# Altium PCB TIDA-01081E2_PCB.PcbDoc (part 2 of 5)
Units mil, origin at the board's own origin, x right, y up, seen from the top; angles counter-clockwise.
Board outline 8611.33 x 3169.64 mil, 4 copper layers (Top Layer, VCC, GND, Bottom Layer), stack 61.6 mil thick; 411 components, 187 nets, 1087 pads, 1987 vias.
Unrouted connection lines stored in the file: 7.
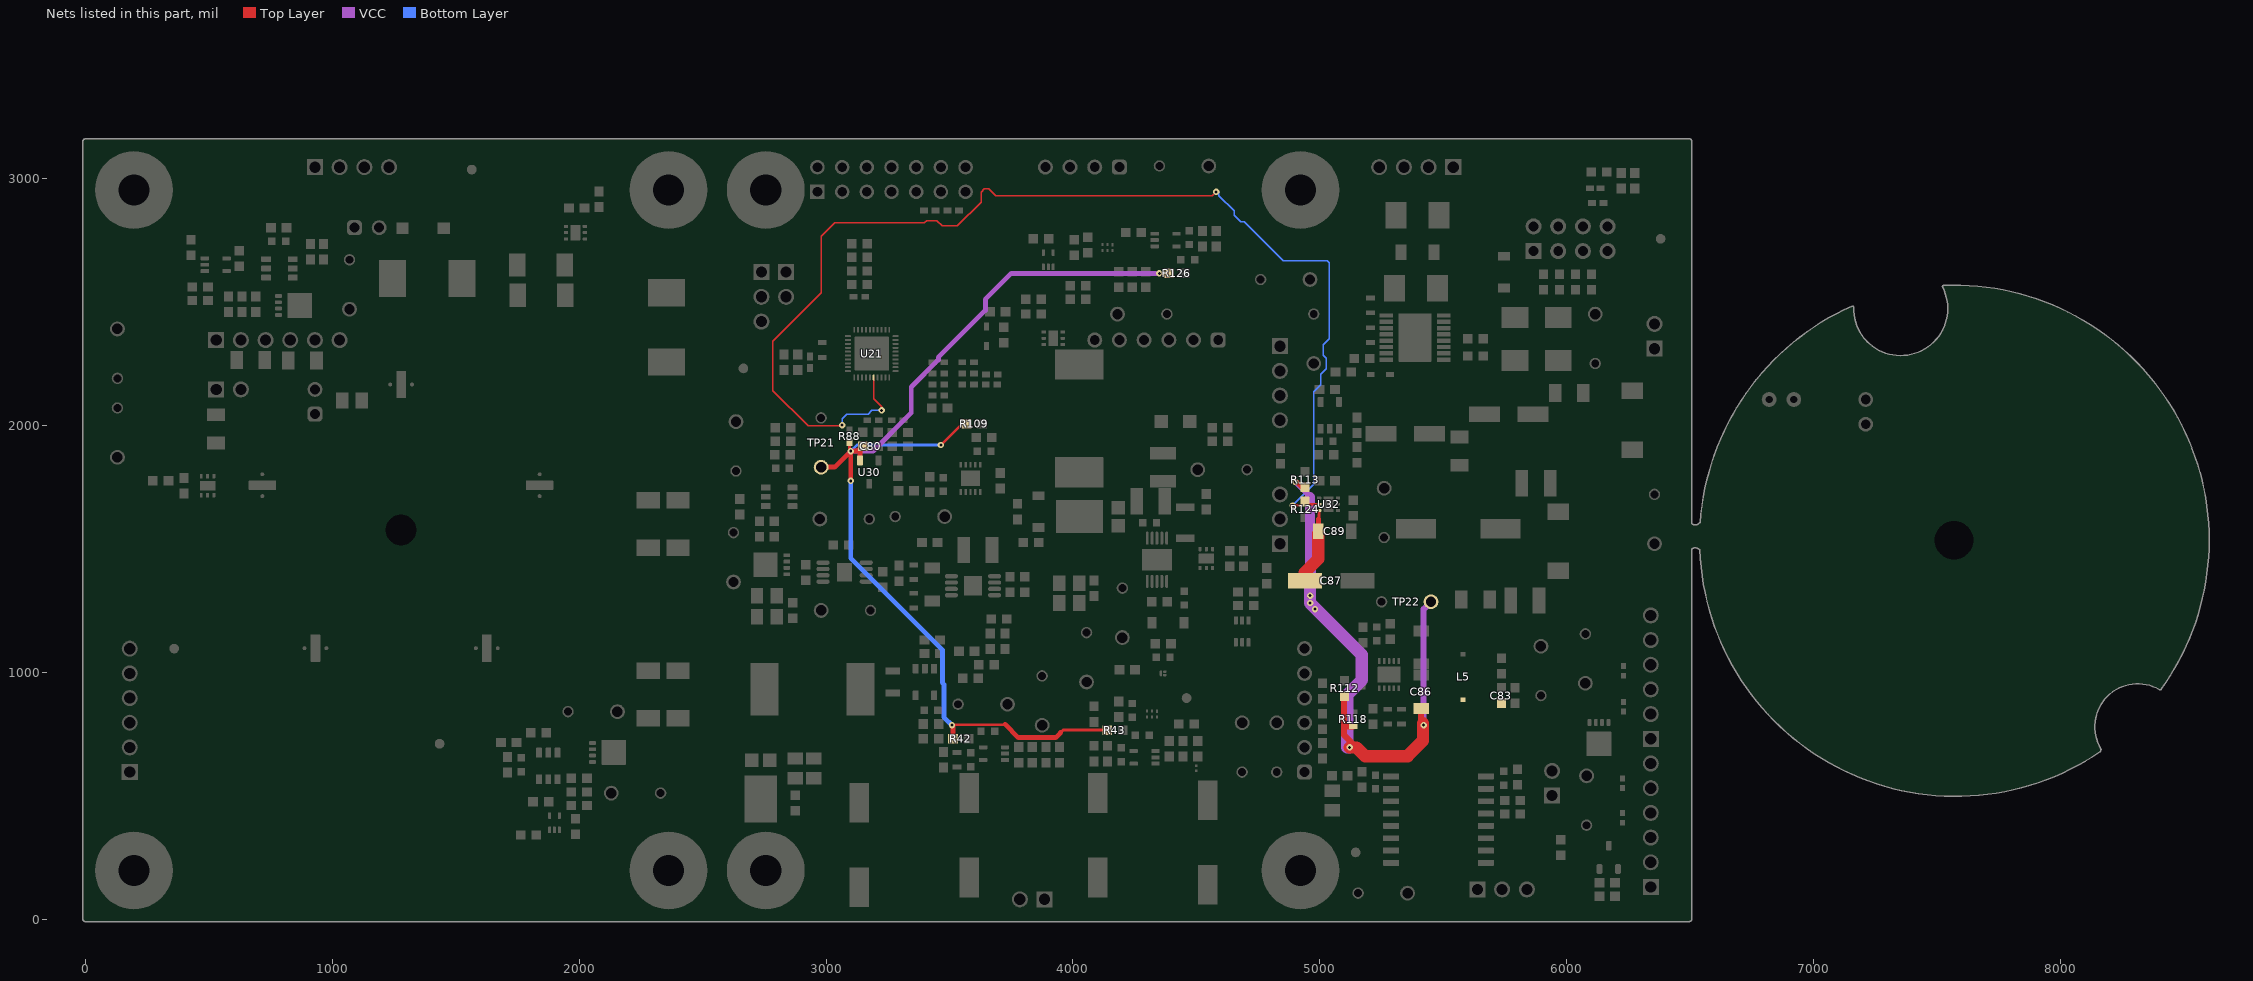
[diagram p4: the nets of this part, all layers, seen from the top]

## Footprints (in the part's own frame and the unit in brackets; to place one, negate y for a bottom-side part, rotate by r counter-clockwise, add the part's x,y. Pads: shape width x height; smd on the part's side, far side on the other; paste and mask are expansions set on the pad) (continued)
LUW_HWQP_White-IHT [mm] "SMD, 3-Leads, Body 3.75x3.75mm"
  round 0.4 smd paste-1 mask+0: 1(0,1.125) 3(0,-1.125)
  rrect10% 2.8x1 smd paste-1 mask+0: 2(0,0)
  rrect11% 1.15x0.9 on Top Paste: ""(-0.725,0) ""(0.725,0)
  Top Layer region: -0.35,-2.3 0.35,-2.3 0.35,-1.4 1.4,-1.4 1.4,-0.85 -1.4,-0.85 -1.4,-1.4 -0.35,-1.4
  Top Layer region: -0.35,2.3 0.35,2.3 0.35,1.4 1.4,1.4 1.4,0.85 -1.4,0.85 -1.4,1.4 -0.35,1.4
  silkscreen extent -2.03,-3.2 2.02,1.92, body extent -1.92,-1.92 1.92,1.92, height 0.6
MMB0207 [mm] "Vishay Beyschlag"
  rect 1.7x2.4 smd: 1(-2.45,0) 2(2.45,0)
  silkscreen extent -1.3,-1.1 1.3,1.1, body extent -2.98,-1.1 2.98,1.1, height 2.2
Net-Tie_10mil [mil] "10mil net tie, no solder mask opening, no solder paste"
  rect 10x10 smd paste-5 mask-5: 1(-10,0) 2(10,0)
  Top Layer region: -6,5 6,5 6,-5 -6,-5
Pb-Free_Overlay_Small [mil]
  silkscreen extent -46,-46 46,46
PowerDI5 [mm] "Diodes Inc recommended land pattern, ap02001.pdf rev 60"
  rect 1.4x1.39 smd: 1(-1.991,0.92) 2(-1.991,-0.92)
  rect 4.86x3.36 smd: 3(1.991,0)
  silkscreen extent -1.7,-2.1 3.8,2.1, body extent -2.27,-2.03 4.33,2.03, height 1.17
PWP0016H_N [mm] "TSOP, 16-Leads, Body 5x4.4mm, Pitch 0.65mm, Thermal Pad 2.48x3.37 mm, IPC Medium Density"
  rrect22% 1.4x0.45 smd: 1(-2.95,2.275) 2(-2.95,1.625) 3(-2.95,0.975) 4(-2.95,0.325) 5(-2.95,-0.325) 6(-2.95,-0.975) 7(-2.95,-1.625) 8(-2.95,-2.275) 9(2.95,-2.275) 10(2.95,-1.625) 11(2.95,-0.975) 12(2.95,-0.325) 13(2.95,0.325) 14(2.95,0.975) 15(2.95,1.625) 16(2.95,2.275)
  rrect6% 3.4x5 smd paste-2 mask-2: 17(0,0)
  rrect4% 2.66x2.46 on Top Solder: 17(0,0)
  rrect4% 2.66x2.46 on Top Paste: 17(0,0)
  silkscreen extent -3.55,-2.55 1.5,2.75, body extent -3.2,-2.5 3.2,2.5, height 1.13
RSB0040B [mm] "QFN, 40-Leads, Body 5x5mm, Pitch 0.4mm, Thermal Pad 3.5x3.5mm, TI Recommended"
  rrect50% 0.6x0.2 smd: 1(-2.45,1.8) 2(-2.45,1.4) 3(-2.45,1) 4(-2.45,0.6) 5(-2.45,0.2) 6(-2.45,-0.2) 7(-2.45,-0.6) 8(-2.45,-1) 9(-2.45,-1.4) 10(-2.45,-1.8) 21(2.45,-1.8) 22(2.45,-1.4) 23(2.45,-1) 24(2.45,-0.6) 25(2.45,-0.2) 26(2.45,0.2) 27(2.45,0.6) 28(2.45,1) 29(2.45,1.4) 30(2.45,1.8)
  rrect50% 0.2x0.6 smd: 11(-1.8,-2.45) 12(-1.4,-2.45) 13(-1,-2.45) 14(-0.6,-2.45) 15(-0.2,-2.45) 16(0.2,-2.45) 17(0.6,-2.45) 18(1,-2.45) 19(1.4,-2.45) 20(1.8,-2.45) 31(1.8,2.45) 32(1.4,2.45) 33(1,2.45) 34(0.6,2.45) 35(0.2,2.45) 36(-0.2,2.45) 37(-0.6,2.45) 38(-1,2.45) 39(-1.4,2.45) 40(-1.8,2.45)
  rrect3% 3.5x3.5 smd paste-1.75: 41(0,0)
  silkscreen extent -2.72,-2.73 2.72,2.73, body extent -2.57,-2.57 2.58,2.58, height 0.81
Samtec_TSW-102-17-x-S [mm] "Header, 2.54mm, 2x1, TH"
  rrect50% 1.53x1.53 hole 1.02: 1(-1.27,0)
  round 1.53 hole 1.02: 2(1.27,0)
  silkscreen extent -2.7,-1.3 2.6,1.6, body extent -2.67,-1.27 2.54,1.27, height 18.29
SDA10A [mm] "SON, 10-Leads, Body 3x3 mm, Pitch 0.5mm, NSC Recommended"
  rect 0.6x0.25 smd paste-0.125 mask+0.051: 1(-1.4,1) 2(-1.4,0.5) 3(-1.4,0) 4(-1.4,-0.5) 5(-1.4,-1) 6(1.4,-1) 7(1.4,-0.5) 8(1.4,0) 9(1.4,0.5) 10(1.4,1)
  rect 1.6x2 smd paste-0.05 mask+0.051: 11(0,0)
  silkscreen extent -2.52,-1.7 1.85,1.75, body extent -1.55,-1.55 1.55,1.55, height 0.8
SM_RADIAL_6.3AMM [mm] "Nichicon 6.3x5.8"
  rect 3.5x1.6 smd: 1(-2.7,0) 2(2.7,0)
  silkscreen extent -3.3,-3.29 3.3,3.31, body extent -3.5,-3.3 3.5,3.3, height 6.11
SM_RADIAL_D8 [mm] "6.3 x 7.7mm:  Panasonic D8"
  rect 3.2x1.6 smd: 1(-2.5,0) 2(2.5,0)
  silkscreen extent -3.4,-3.4 3.4,3.4, body extent -3.4,-3.4 3.4,3.4, height 8.01
SM_RADIAL_G [mm] "10 x 10.2mm:  Panasonic G"
  rect 4.1x2 smd: 1(-4.35,0) 2(4.35,0)
  silkscreen extent -5.35,-5.35 5.35,5.35, body extent -5.25,-5.25 5.25,5.25, height 10.5
SMB [mil] "Molded Diode, 2-Leads, Body 5.4x3.6mm, IPC Medium Density, based on OnSemi component dimensions"
  rect 85x107.99 smd: 1(-87.01,0) 2(87.01,0)
  silkscreen extent -155,-82 125,82, body extent -106,-71 106,71, height 91
SMB-Bi [mil] "Molded Diode, 2-Leads, Body 5.4x3.6mm, IPC Medium Density, based on OnSemi component dimensions"
  rect 85x107.99 smd: 1(-87.01,0) 2(87.01,0)
  silkscreen extent -125,-79 125,79, body extent -104,-73 104,73, height 89
SMC [mil] "Molded Diode, 2-Leads, Body 6.9x5.8mm, IPC Medium Density, based on OnSemi component dimensions and land patterns"
  rect 110x150 smd: 1(-140.49,0) 2(140.49,0)
  silkscreen extent -221,-124 189,123, body extent -156,-116 156,116, height 91
SNT-100-BK-G [mil] "Samtec STEP model"
  round 1 on Mech3: 0(0,0)
  body extent -100,-50 100,50, height 344
SOD-123 [mm] "On Semi recommended land pattern"
  rect 0.915x1.22 smd: 1(-1.637,0) 2(1.637,0)
  silkscreen extent -2.74,-1.17 2.03,1.17, body extent -1.93,-0.9 1.93,0.9, height 1.35
SOD-523 [mm] "NXP Semiconductor recommended land pattern, nominal STEP model"
  rect 0.8x0.6 smd paste-0.05: 1(-0.55,0) 2(0.55,0)
  silkscreen extent -1.65,-0.66 1.2,0.66, body extent -0.8,-0.4 0.8,0.4, height 0.72
SOT-23 [mm] "SOT23, 3-Leads, Body 2.9x1.3mm, Pitch 0.95mm, Lead Span 2.5mm, IPC Medium Density"
  rrect50% 1x0.6 smd: 1(-1.2,0.95) 2(-1.2,-0.95) 3(1.2,0)
  silkscreen extent -1.62,-1.5 0.7,1.5, body extent -1.16,-1.45 1.21,1.45, height 1
Sullins_PPPC041LFBN-RC [mm] "Receptacle, 2.54mm, 4x1, TH"
  rrect50% 1.55x1.55 hole 1.02: 1(-3.81,0)
  round 1.55 hole 1.02: 2(-1.27,0) 3(1.27,0) 4(3.81,0)
  silkscreen extent -5.33,-1.27 5.33,1.7, body extent -5.33,-1.27 5.33,1.27, height 8.5
Sullins_PPPC061LFBN-RC [mm] "Receptacle, 2.54mm, 6x1, Gold, TH"
  rrect50% 1.55x1.55 hole 1.02: 1(-6.35,0)
  round 1.55 hole 1.02: 2(-3.81,0) 3(-1.27,0) 4(1.27,0) 5(3.81,0) 6(6.35,0)
  silkscreen extent -7.87,-1.27 7.87,1.7, body extent -7.87,-1.27 7.87,1.27, height 8.5
Sullins_SBH11-PBPC-D07-RA-BK [mm] "Header (Shrouded), 2.54 mm, 7x2, R/A, TH"
  rect 1.5x1.5 hole 1: 1(-7.62,-1.27)
  round 1.5 hole 1: 2(-7.62,1.27) 3(-5.08,-1.27) 4(-5.08,1.27) 5(-2.54,-1.27) 6(-2.54,1.27) 7(0,-1.27) 8(0,1.27) 9(2.54,-1.27) 10(2.54,1.27) 11(5.08,-1.27) 12(5.08,1.27) 13(7.62,-1.27) 14(7.62,1.27)
  silkscreen extent -12.74,-3.05 12.74,12.21, body extent -12.74,-1.56 12.74,12.21, height 9.3
TESTPOINT_PIGTAIL [mil] "Pigtail"
  round 60 hole 42: 1(0,0)
  round 46 hole 32: 2(0,-200)
  silkscreen extent -50,-233 50,50
TP_SM_1MM [mm] "1mm Test Point, SMT"
  round 1 smd paste-0.5: 1(0,0)
WE-LHMI_1365 [mm] "SMD, 2-Leads, Body 12.5x12.5mm"
  rrect3% 3.1x5 smd: 1(-5.55,0) 2(5.55,0)
  silkscreen extent -6.5,-6.5 6.5,6.5, body extent -6.4,-6.4 6.4,6.4, height 6.5
WE-PD_1210 [mm] "Wurth Elektronik recommended land pattern"
  rect 2.9x5.4 smd: 1(-4.95,0) 2(4.95,0)
  silkscreen extent -6,-6 6,6, body extent -6,-6 6,6, height 10.01
WE-TPC_4828 [mm] "Wurth Elektronik recommended land pattern"
  rect 0.5x0.5 smd: 1(-2.35,0) 2(2.325,0)
  Top Layer region: 0.75,1.64 1.005,1.504 1.279,1.279 1.504,1.005 1.671,0.692 1.774,0.353 1.809,0 1.774,-0.353 1.671,-0.692 1.504,-1.005 1.279,-1.279 1.005,-1.504 0.75,-1.64 0.75,-2.65 2.75,-2.65 2.75,2.65 0.75,2.65
  Top Layer region: -0.75,1.64 -1.005,1.504 -1.279,1.279 -1.504,1.005 -1.671,0.692 -1.774,0.353 -1.809,0 -1.774,-0.353 -1.671,-0.692 -1.504,-1.005 -1.279,-1.279 -1.005,-1.504 -0.75,-1.64 -0.75,-2.65 -2.75,-2.65 -2.75,2.65 -0.75,2.65
  silkscreen extent -0.5,-2.6 0.5,2.63, body extent -2.5,-2.5 2.5,2.5, height 2
WURTH_61300211121 [mm] "Header, 2.54mm, 2x1, TH"
  rect 1.65x1.65 hole 1.15: 1(-1.27,0)
  round 1.65 hole 1.15: 2(1.27,0)
  silkscreen extent -2.54,-1.27 2.54,1.6, body extent -2.54,-1.27 2.54,1.27, height 8.54
WURTH_61300311121 [mm] "Header, 2.54mm, 3x1, TH"
  rect 1.65x1.65 hole 1.15: 1(-2.54,0)
  round 1.65 hole 1.15: 2(0,0) 3(2.54,0)
  silkscreen extent -3.81,-1.27 3.81,1.6, body extent -3.81,-1.27 3.81,1.27, height 8.54
WURTH_61300411121 [mm] "Header, 2.54mm, 4x1, TH"
  rect 1.65x1.65 hole 1.15: 1(-3.81,0)
  round 1.65 hole 1.15: 2(-1.27,0) 3(1.27,0) 4(3.81,0)
  silkscreen extent -5.08,-1.27 5.08,1.6, body extent -5.08,-1.27 5.08,1.27, height 8.54
WURTH_61300611121 [mm] "Header, 2.54mm, 6x1, TH"
  rect 1.65x1.65 hole 1.15: 1(-6.35,0)
  round 1.65 hole 1.15: 2(-3.81,0) 3(-1.27,0) 4(1.27,0) 5(3.81,0) 6(6.35,0)
  silkscreen extent -7.62,-1.27 7.62,1.6, body extent -7.62,-1.27 7.62,1.27, height 8.54
YJM0003A [mm] "SMT, 3-Leads, Body 0.69x0.6mm"
  rrect80% 0.35x0.25 smd paste-0.2 mask-0.05: 1(-0.175,0.175) 2(-0.175,-0.175)
  rrect50% 0.25x0.2 on Top Paste: 1(-0.175,0.2) 2(-0.175,-0.2)
  rrect80% 0.25x0.6 smd paste-0.05 mask-0.05: 3(0.225,0)
  body extent -0.34,-0.3 0.35,0.3, height 0.35

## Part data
C1 C2 C3 C12 C13 C14 C23 C24 C31 C32 C39 C41 C42 C44 C45 C47 C48 C73 C75 C77 C78 C79 C80: "CAP, CERM, 1 µF, 16 V, +/- 10%, X7R, 0603", Cap_Case=0603, Manufacturer=MuRata, Supplier Part Number 1=490-10734-1-ND, TempCo=X7R, Tolerance_%=10, Value1=Unknown, Value2=16V, ValueDisplayed=1µF
C4 C17 C22 C33 C34 C35 C36 C40 C43 C46 C63 C64 C74 C76 C81 C88 C92 C93: "CAP, CERM, 0.1 µF, 16 V, +/- 10%, X7R, 0603_095", Cap_Case=0603, Manufacturer=MuRata, Supplier Part Number 1=490-8015-1-ND, TempCo=X7R, Tolerance_%=10, Value1=Unknown, Value2=16V, ValueDisplayed=0.1µF
C5: "CAP, CERM, 4.7 µF, 80 V,+/- 10%, X7R, 1210", Cap_Case=1210, Manufacturer=MuRata, Supplier Part Number 1=490-9972-1-ND, TempCo=X7R, Tolerance_%=10, Value1=Unknown, Value2=80V, ValueDisplayed=4.7µF
C6: "CAP, CERM, 0.1 µF, 100 V, +/- 10%, X7R, 0603", Cap_Case=0603, Manufacturer=MuRata, Supplier Part Number 1=490-3285-1-ND, TempCo=X7R, Tolerance_%=10, Value1=Unknown, Value2=100V, ValueDisplayed=0.1µF
C7 C18 C30: "CAP, CERM, 2200 pF, 100 V, +/- 10%, X7R, AEC-Q200 Grade 1, 0603", Cap_Case=0603, Manufacturer=TDK, Supplier Part Number 1=445-5808-1-ND, TempCo=X7R, Tolerance_%=10, Value1="0.923948 ohm", Value2=100V, ValueDisplayed=2200pF
C8: "CAP, CERM, 470 pF, 50 V, +/- 5%, C0G/NP0, AEC-Q200 Grade 1, 0603", Cap_Case=0603, Manufacturer=MuRata, Supplier Part Number 1=490-4965-1-ND, TempCo=C0G/NP0, Tolerance_%=5, Value1=Unknown, Value2=50V, ValueDisplayed=470pF
C9: "CAP, CERM, 470 pF, 50 V, +/- 5%, C0G/NP0, 0603_095", Cap_Case=0603, Manufacturer=MuRata, Supplier Part Number 1=490-4965-1-ND, TempCo=C0G/NP0, Tolerance_%=5, Value1=Unknown, Value2=50V, ValueDisplayed=470pF
C10: "CAP, CERM, 0.1 µF, 10 V, +/- 10%, X7R, 0603", Cap_Case=0603, Manufacturer=Kemet, Supplier Part Number 1=399-1095-1-ND, TempCo=X7R, Tolerance_%=10, Value1=Unknown, Value2=10V, ValueDisplayed=0.1µF
C11 C53 C56 C58 C60 C65 C66: "CAP, CERM, 10 µF, 10 V, +/- 20%, X7R, 0603", Cap_Case=0603, Manufacturer=MuRata, Supplier Part Number 1=81-GRM188Z71A106MA3D, TempCo=X7R, Tolerance_%=20, Value1=Unknown, Value2=10V, ValueDisplayed=10µF
C15 C49 C50 C51 C52: "CAP, CERM, 0.01 µF, 16 V, +/- 10%, X7R, 0402", Cap_Case=0402, Manufacturer=TDK, Supplier Part Number 1=445-1262-1-ND, TempCo=X7R, Tolerance_%=10, Value1="0.0623 ohm", Value2=16V, ValueDisplayed=0.01µF
C16 C82: "CAP, CERM, 10 µF, 10 V, +/- 10%, X7T, 0603", Cap_Case=0603, Manufacturer=MuRata, Supplier Part Number 1=490-10987-1-ND, TempCo=X7T, Tolerance_%=10, Value1=Unknown, Value2=10V, ValueDisplayed=10µF
C19: "CAP, CERM, 0.01 µF, 50 V, +/- 10%, X7R, 0603", Cap_Case=0603, Manufacturer="Samsung Electro-Mechanics", Supplier Part Number 1=1276-1921-1-ND, TempCo=X7R, Tolerance_%=10, Value1=Unknown, Value2=50V, ValueDisplayed=0.01µF
C20: "CAP, CERM, 22 µF, 25 V, +/- 10%, X5R, 1206", Cap_Case=1206, Manufacturer=MuRata, Supplier Part Number 1=490-5527-1-ND, TempCo=X5R, Tolerance_%=10, Value1=Unknown, Value2=25V, ValueDisplayed=22µF
C21 C68 C69: "CAP, CERM, 4.7 µF, 80 V, +/- 10%, X7R, 1210", Cap_Case=1210, Manufacturer=MuRata, Supplier Part Number 1=490-9972-1-ND, TempCo=X7R, Tolerance_%=10, Value1=Unknown, Value2=80V, ValueDisplayed=4.7µF
C25 C26 C27 C28 C72: "CAP, AL, 100 µF, 63 V, +/- 20%, 0.35 ohm, AEC-Q200 Grade 2, SMD", Cap_Case=G, Manufacturer=Panasonic, Supplier Part Number 1=PCE3819CT-ND, Tolerance_%=20, Value1="0.35 ohm", Value2=63V, ValueDisplayed=100µF
C29: "CAP, CERM, 47 pF, 50 V, +/- 5%, C0G/NP0, AEC-Q200 Grade 1, 0603", Cap_Case=0603, Manufacturer=TDK, Supplier Part Number 1=445-5636-1-ND, TempCo=C0G/NP0, Tolerance_%=5, Value1=Unknown, Value2=50V, ValueDisplayed=47pF
C37: "CAP, CERM, 150 pF, 50 V,+/- 5%, C0G/NP0, 0603", Cap_Case=0603, Manufacturer=Kemet, Supplier Part Number 1=399-1063-1-ND, TempCo=C0G/NP0, Tolerance_%=5, Value1=Unknown, Value2=50V, ValueDisplayed=150pF
C38: "CAP, CERM, 100 pF, 50 V,+/- 5%, C0G/NP0, 0603", Cap_Case=0603, Manufacturer=AVX, Supplier Part Number 1=478-1175-1-ND, TempCo=C0G/NP0, Tolerance_%=5, Value1="0.119 ohm", Value2=50V, ValueDisplayed=100pF
C54 C57 C59 C61: "CAP, CERM, 0.1 µF, 10 V, +/- 10%, X7R, 0402", Cap_Case=0402, Manufacturer=MuRata, Supplier Part Number 1=GRM155R71A104KA01D-ND, TempCo=X7R, Tolerance_%=10, Value1=Unknown, Value2=10V, ValueDisplayed=0.1µF
C55: "CAP, CERM, 0.47 µF, 6.3 V, +/- 10%, X7R, 0603", Cap_Case=0603, Manufacturer=MuRata, Supplier Part Number 1=GRM188R70J474KA01D-ND, TempCo=X7R, Tolerance_%=10, Value1=Unknown, Value2=6.3V, ValueDisplayed=0.47µF
C62: "CAP, CERM, 2200 pF, 6.3 V, +/- 10%, X7R, 0402", Cap_Case=0402, Manufacturer=MuRata, Supplier Part Number 1=GRM155R70J222KA01D-ND, TempCo=X7R, Tolerance_%=10, Value1=Unknown, Value2=6.3V, ValueDisplayed=2200pF
C67 C84: "CAP, CERM, 1 µF, 100 V, +/- 10%, X7R, 1206", Cap_Case=1206, Manufacturer=MuRata, Supplier Part Number 1=490-3909-1-ND, TempCo=X7R, Tolerance_%=10, Value1=Unknown, Value2=100V, ValueDisplayed=1µF
C70 C71: "CAP, AL, 22 µF, 63 V, +/- 20%, 1.2 ohm, AEC-Q200 Grade 2, SMD", Cap_Case=D8, Manufacturer=Panasonic, Supplier Part Number 1=PCE3821CT-ND, Tolerance_%=20, Value1="1.2 ohm", Value2=63V, ValueDisplayed=22µF
C83: "CAP, CERM, 560 pF, 50 V, +/- 5%, C0G/NP0, 0603", Cap_Case=0603, Manufacturer=Kemet, Supplier Part Number 1=399-3287-1-ND, TempCo=C0G/NP0, Tolerance_%=5, Value1=Unknown, Value2=50V, ValueDisplayed=560pF
C85: "CAP, CERM, 680 pF, 50 V,+/- 5%, C0G/NP0, 0603", Cap_Case=0603, Manufacturer=Kemet, Supplier Part Number 1=399-3289-1-ND, TempCo=C0G/NP0, Tolerance_%=5, Value2=50V, ValueDisplayed=680pF
C86 C89: "CAP, CERM, 33 µF, 25 V, +/- 20%, X5R, 1206", Cap_Case=1206, Manufacturer=TDK, Supplier Part Number 1=445-8046-1-ND, TempCo=X5R, Tolerance_%=20, Value1="0.002648 ohm", Value2=25V, ValueDisplayed=33µF
C87: "CAP, AL, 100 µF, 10 V, +/- 20%, 0.44 ohm, SMD", Cap_Case=6.3x5.8, Manufacturer=Nichicon, Supplier Part Number 1=493-2248-1-ND, Tolerance_%=20, Value1="0.44 ohm", Value2=10V, ValueDisplayed=100µF
C90: "CAP, CERM, 0.1 µF, 16 V, +/- 10%, X7R, 0603", Cap_Case=0603, Manufacturer=MuRata, Supplier Part Number 1=490-1532-1-ND, TempCo=X7R, Tolerance_%=10, Value1=Unknown, Value2=16V, ValueDisplayed=0.1µF
C91: "CAP, CERM, 2.2 µF, 100 V,+/- 10%, X7R, AEC-Q200 Grade 1, 1210", Cap_Case=1210, Manufacturer=TDK, Supplier Part Number 1=445-5866-1-ND, TempCo=X7R, Tolerance_%=10, Value1="0.00173 ohm", Value2=100V, ValueDisplayed=2.2µF
C94: "CAP, CERM, 10 pF, 50 V,+/- 5%, C0G/NP0, 0603", Cap_Case=0603, Manufacturer=AVX, Supplier Part Number 1=478-1163-1-ND, TempCo=C0G/NP0, Tolerance_%=5, Value1="0.403 ohm", Value2=50V, ValueDisplayed=10pF
C95: "CAP, CERM, 680 pF, 100 V,+/- 5%, C0G/NP0, 1206", Cap_Case=1206, Manufacturer=AVX, Supplier Part Number 1=478-1449-1-ND, TempCo=C0G/NP0, Tolerance_%=5, Value1="0.281 ohm", Value2=100V, ValueDisplayed=680pF
C96: "CAP, CERM, 10 µF, 35 V,+/- 10%, X5R, 0805", Cap_Case=0805, Manufacturer=MuRata, Supplier Part Number 1=490-10514-1-ND, TempCo=X5R, Tolerance_%=10, Value2=35V, ValueDisplayed=10µF
D1: "Diode, Hyperfast, 200 V, 2 A, AEC-Q101, DO-219AB", Manufacturer=Vishay-Semiconductor, Supplier Part Number 1=VS-2EFH02HM3/IGICT-ND, Value1=2A, Value2=0.95V
D2 D5: "Diode, Switching, 100 V, 0.2 A, SOD-123", Manufacturer="ON Semiconductor", Supplier Part Number 1=MMSD4148T1GOSCT-ND, Value1=0.2A, Value2=1V
D3 D6: "Diode, Schottky, 100 V, 3 A, AEC-Q101, PowerDI5", Manufacturer="Diodes Inc.", Supplier Part Number 1=PDS3100Q-13DICT-ND, Value1=3A, Value2=0.76V
D7 D10: "Diode, Schottky, 40 V, 3 A, SMC", Manufacturer="ON Semiconductor", Supplier Part Number 1=MBRS340T3GOSCT-ND, Value1=3A, Value2=0.525V
D9 D11 D14 D15 D16: "LED, White, SMD", Color=White, Manufacturer=OSRAM, Supplier Part Number 1="LUW HWQP-8M7N-EBVF46FCBB46-8E8H-ND", Value1=W, Value2=3.05V
D17 D18: "Diode, TVS, Bi, 36 V, 76 Vc, AEC-Q101, SMB", Manufacturer=STMicroelectronics, Supplier Part Number 1=497-12193-1-ND, Value1=W
D19: "Diode, TVS, Uni, 36 V, AEC-Q101, SMB", Manufacturer=Semtech, Supplier Part Number 1=497-11809-1-ND, Value1=W
D20: "Diode, Schottky, 100 V, 1.9 A, SMB", Manufacturer=Vishay-Semiconductor, Supplier Part Number 1=VSSB310-E3/52TGICT-ND, Value1=1.9A, Value2=0.56V
D21 D24: "Diode, Switching, 75 V, 0.3 A, SOD-523F", Manufacturer="Fairchild Semiconductor", Supplier Part Number 1=1N4148WTCT-ND, Value1=0.3A, Value2=V
D22: "Diode, Zener, 3 V, 500 mW, SOD-123", Manufacturer="ON Semiconductor", Power_W=0.5, Supplier Part Number 1=MMSZ4683T1GOSCT-ND, Value1=0.5W
D23: "Diode, Schottky, 30 V, 0.2 A, AEC-Q101, SOD-523", Manufacturer="ON Semiconductor", Supplier Part Number 1=RB521S30T1GOSCT-ND, Value1=0.2A, Value2=0.5V
FID1 FID2 FID3 FID4 FID5 FID6: "Fiducial mark.  There is nothing to buy or mount.", Manufacturer=N/A
H1 H2 H3 H4 H9 H10 H11 H12: "Standoff, Hex, Male/Female, 4-40, Nylon, 1/2\"", Manufacturer=Keystone, Supplier Part Number 1=36-4802-ND
H5 H6 H7 H8: "Standoff, Hex, 0.5\"L #4-40 Nylon", Alternate Manufacturer=-, Manufacturer=Keystone, Supplier Part Number 1=1902CK-ND
H14: library part CMP-0003947-1, "Hex Nuts: M3 X .5MM pitch DIN 934 A2 - 304 Stainless", Manufacturer="InStock Fasteners"
H16: library part CMP-0078705-1, "Heat Sink, 10x10x6.5mm", Manufacturer="Fischer Elektronik", Supplier Part Number 1=17T5915
J1 J9: "Receptacle, 2.54mm, 6x1, Gold, TH", Color=Black, Current_A=3, Manufacturer="Sullins Connector Solutions", Supplier Part Number 1=S7039-ND, Voltage_V=250
J2 J7 J19: "Header, 2.54 mm, 4x1, Gold, TH", Manufacturer="Wurth Elektronik", Supplier Part Number 1=732-5317-ND
J3 J11 J17: "Header, 2.54 mm, 3x1, Gold, TH", Manufacturer="Wurth Elektronik", Supplier Part Number 1=732-5316-ND
J4 J6 J15 J16: "Header, 2.54 mm, 6x1, Gold, TH", Manufacturer="Wurth Elektronik", Supplier Part Number 1=732-5319-ND
J5 J18: library part CMP-0077742-1, "Header, 2.54mm, 2x1, Gold, TH", Color=Black, Manufacturer=Samtec, Supplier Part Number 1=SAM1061-02-ND
J8 J12 J14 J21 J22: "Header, 2.54 mm, 2x1, Gold, TH", Manufacturer="Wurth Elektronik", Supplier Part Number 1=732-5315-ND
J10: "Receptacle, 2.54mm, 4x1, Gold, TH", Color=Black, Current_A=3, Manufacturer="Sullins Connector Solutions", Supplier Part Number 1=S7037-ND, Voltage_V=250
J13: "Header (Shrouded), 2.54 mm, 7x2, Gold, R/A, TH", Manufacturer="Sullins Connector Solutions", Supplier Part Number 1=S9178-ND
J20: "Header, 100mil, 4x2, Tin, TH", Color=Black, Current_A=3, Manufacturer="Sullins Connector Solutions", Supplier Part Number 1=S2012E-04-ND, Voltage_V=1800
L1: "Inductor, Wirewound, Powdered Iron, 100 µH, 2.6 A, 0.165 ohm, SMD", Manufacturer="Wurth Elektronik", Value1="0.165 ohm", Value2=2.6A, ValueDisplayed=100µH
L2: "Inductor, Shielded Drum Core, Ferrite, 470 µH, 1.4 A, 0.56 ohm, SMD", Manufacturer="Wurth Elektronik", Supplier Part Number 1=732-1699-1-ND, Value1="0.56 ohm", Value2=1.4A, ValueDisplayed=470µH
L3 L4: "Inductor, Shielded, Ferrite, 33 µH, 1.55 A, 0.13 ohm, SMD", Manufacturer=TDK, Supplier Part Number 1=445-15680-1-ND, Value1="0.13 ohm", Value2=1.55A, ValueDisplayed=33µH
L5: "Inductor, Shielded Drum Core, Metal Composite, 220 µH, 0.2 A, 1.008 ohm, SMD", Manufacturer="Wurth Elektronik", Supplier Part Number 1=732-3661-1-ND, Value1="1.008 ohm", Value2=0.2A, ValueDisplayed=220µH
L6: "Ferrite Bead, 60 ohm @ 100 MHz, 6 A, 1806", Manufacturer="Wurth Elektronik", Supplier Part Number 1=732-1635-1-ND, Value1="0.01 ohm", Value2=6A, ValueDisplayed="60 ohm"
L7: "Ferrite Bead, 10 ohm @ 100 MHz, 3 A, 0805", Manufacturer="Wurth Elektronik", Supplier Part Number 1=732-4635-1-ND, Value1="0.025 ohm", Value2=3A, ValueDisplayed="10 ohm"
LBL1: library part THT-14-423-10, "Thermal Transfer Printable Labels, 0.650\" W x 0.200\" H - 10,000 per roll", Alternate Manufacturer=-, Manufacturer=Brady, Supplier Part Number 1=2065596
Logo2 Logo2_1 Logo11: library part Pb-Free
Logo3 Logo3_1 Logo12: library part FCC_disclaimer, "FCC_disclaimer"
LOGO4 LOGO6 LOGO7: library part IEC_HotSurface, "IEC 61010-1 Hot Surface Warning"
LOGO5 LOGO5_1 LOGO8: library part LED_Warning, "LED Warning Symbol"
Logo9: library part IEC_Caution, "IEC 61010-1 Caution Warning"
NT1: "Single point connection between nets."
Q1: "MOSFET, N-CH, 20 V, 0.5 A, YJM0003A (PICOSTAR-3)", Alternate Manufacturer=None, Manufacturer="Texas Instruments", Supplier Part Number 1=296-44373-1-ND, Value1="1.46 ohm", Value2="0.216 nC"
Q2 Q3 Q4 Q5: "MOSFET, N-CH, 60 V, 35 A, DNH0008A (VSONP-8)", Alternate Manufacturer=None, Manufacturer="Texas Instruments", Supplier Part Number 1=CSD18543Q3A-ND, Value1="0.012 ohm", Value2="11.1 nC"
Q6: library part "BC817-25,215, Nexperia", "Transistor, NPN, 45 V, 0.5 A, SOT-23", Manufacturer=Nexperia, Supplier Part Number 1=568-1630-1-ND, Value1="0.5 A", Value2=400
R1 R2 R55 R56: "RES, 100, 1%, 0.1 W, 0603", Manufacturer="Yageo America", Power_W=0.1, Supplier Part Number 1=311-100HRCT-ND, TempCo="200 ppm/C", Tolerance_%=1, Value1=1%, Value2=0.1W, Value_Code=100R, ValueDisplayed=100
R3: "RES, 0.082, 1%, 0.75 W, AEC-Q200 Grade 0, 1206", Manufacturer="Susumu Co Ltd", Power_W=0.75, Supplier Part Number 1=408-1581-1-ND, TempCo="50 ppm/C", Tolerance_%=1, Value1=1%, Value2=0.75W, Value_Code=R082, ValueDisplayed=0.082
R4 R5 R23 R26 R31 R32: "RES, 10.0, 1%, 0.5 W, AEC-Q200 Grade 0, 0805", Manufacturer=Panasonic, Power_W=0.5, Supplier Part Number 1=P18937CT-ND, TempCo="300 ppm/C", Tolerance_%=1, Value1=1%, Value2=0.5W, Value_Code=10R0, ValueDisplayed=10.0
R6 R12 R36 R42 R43 R59 R66 R99 R126: "RES, 10.0 k, 1%, 0.1 W, 0603", Manufacturer="Yageo America", Power_W=0.1, Supplier Part Number 1=311-10.0KHRCT-ND, TempCo="200 ppm/C", Tolerance_%=1, Value1=1%, Value2=0.1W, Value_Code=10k0, ValueDisplayed=10.0k
R7 R8 R10 R71 R72 R73: "RES, 4.87 k, 1%, 0.1 W, 0603", Manufacturer="Yageo America", Power_W=0.1, Supplier Part Number 1=311-4.87KHRCT-ND, TempCo="200 ppm/C", Tolerance_%=1, Value1=1%, Value2=0.1W, Value_Code=4k87, ValueDisplayed=4.87k
R9 R11: "RES, 21.5 k, 1%, 0.1 W, 0603", Manufacturer=Vishay-Dale, Power_W=0.1, Supplier Part Number 1=541-21.5KHCT-ND, TempCo="100 ppm/C", Tolerance_%=1, Value1=1%, Value2=0.1W, Value_Code=21k5, ValueDisplayed=21.5k
R13: "RES, 34.8 k, 1%, 0.1 W, 0603", Manufacturer=Vishay-Dale, Power_W=0.1, Supplier Part Number 1=541-34.8KHCT-ND, TempCo="100 ppm/C", Tolerance_%=1, Value1=1%, Value2=0.1W, Value_Code=34k8, ValueDisplayed=34.8k
R14 R15 R17 R18 R37 R38 R44 R46 R57 R62 R63 R69: "RES, 51.1, 1%, 0.1 W, 0603", Manufacturer="Yageo America", Power_W=0.1, Supplier Part Number 1=311-51.1HRCT-ND, TempCo="200 ppm/C", Tolerance_%=1, Value1=1%, Value2=0.1W, Value_Code=51R1, ValueDisplayed=51.1
R16: "RES, 3.74 k, 1%, 0.1 W, 0603", Manufacturer=Vishay-Dale, Power_W=0.1, Supplier Part Number 1=541-3.74KHCT-ND, TempCo="100 ppm/C", Tolerance_%=1, Value1=1%, Value2=0.1W, Value_Code=3k74, ValueDisplayed=3.74k
R19 R28 R29 R30 R51 R58 R60 R64 R68 R89 R90 R119 R127: "RES, 0, 5%, 0.1 W, 0603", Manufacturer="Yageo America", Power_W=0.1, Supplier Part Number 1=311-0.0GRCT-ND, TempCo="200 ppm/C", Tolerance_%=5, Value1=5%, Value2=0.1W, Value_Code=0000, ValueDisplayed=0
R20: "RES, 0.1, 1%, 0.5 W, AEC-Q200 Grade 0, 0805", Manufacturer="Susumu Co Ltd", Power_W=0.5, Supplier Part Number 1=408-1556-1-ND, TempCo="50 ppm/C", Tolerance_%=1, Value1=1%, Value2=0.5W, Value_Code=R100, ValueDisplayed=0.1
R21 R39 R40 R125: "RES, 10.0, 1%, 0.1 W, 0603", Manufacturer="Yageo America", Power_W=0.1, Supplier Part Number 1=311-10.0HRCT-ND, TempCo="200 ppm/C", Tolerance_%=1, Value1=1%, Value2=0.1W, Value_Code=10R0, ValueDisplayed=10.0
R22 R24 R111 R114: "RES, 1.00 k, 1%, 0.1 W, 0603", Manufacturer="Yageo America", Power_W=0.1, Supplier Part Number 1=311-1.00KHRCT-ND, TempCo="200 ppm/C", Tolerance_%=1, Value1=1%, Value2=0.1W, Value_Code=1k00, ValueDisplayed=1.00k
R25 R118: "RES, 100 k, 0.5%, 0.0625 W, 0603", Manufacturer="Susumu Co Ltd", Power_W=0.0625, Supplier Part Number 1=RR08P100KDCT-ND, TempCo="25 ppm/C", Tolerance_%=0.5, Value1=0.5%, Value2=0.0625W, Value_Code=100k
R27: "RES, 21.5 k, 0.5%, 0.0625 W, 0603", Manufacturer="Susumu Co Ltd", Power_W=0.0625, Supplier Part Number 1=RR08P21.5KDCT-ND, TempCo="25 ppm/C", Tolerance_%=0.5, Value1=0.5%, Value2=0.0625W, Value_Code=21k5, ValueDisplayed=21.5k
R33: "RES, 4.22 k, 1%, 0.1 W, 0603", Manufacturer=Vishay-Dale, Power_W=0.1, Supplier Part Number 1=541-4.22KHCT-ND, TempCo="100 ppm/C", Tolerance_%=1, Value1=1%, Value2=0.1W, Value_Code=4k22, ValueDisplayed=4.22k
R34 R35: "RES, 15, 5%, 0.1 W, 0603", Manufacturer=Vishay-Dale, Power_W=0.1, Supplier Part Number 1=541-15GCT-ND, TempCo="200 ppm/C", Tolerance_%=5, Value1=5%, Value2=0.1W, Value_Code=15R0, ValueDisplayed=15
R41: "RES, 16.9 k, 1%, 0.1 W, 0603", Manufacturer=Vishay-Dale, Power_W=0.1, Supplier Part Number 1=541-16.9KHCT-ND, TempCo="100 ppm/C", Tolerance_%=1, Value1=1%, Value2=0.1W, Value_Code=16k9, ValueDisplayed=16.9k
R45: "RES, 4.02 k, 1%, 0.1 W, 0603", Manufacturer=Vishay-Dale, Power_W=0.1, Supplier Part Number 1=541-4.02KHCT-ND, TempCo="100 ppm/C", Tolerance_%=1, Value1=1%, Value2=0.1W, Value_Code=4k02, ValueDisplayed=4.02k
R47 R84 R87: "RES, 10.0 k, 1%, 0.1 W, 0603", Manufacturer=Vishay-Dale, Power_W=0.1, Supplier Part Number 1=541-10.0KHCT-ND, TempCo="100 ppm/C", Tolerance_%=1, Value1=1%, Value2=0.1W, Value_Code=10k0, ValueDisplayed=10.0k
R48: "RES, 100 k, 0.1%, 0.1 W, 0603", Manufacturer="Yageo America", Power_W=0.1, Supplier Part Number 1=603-RT0603BRD07100KL, TempCo="25 ppm/C", Value1=0.1%, Value2=0.1W, Value_Code=100k
R49: "RES, 150 k, 0.1%, 0.1 W, 0603", Manufacturer="Susumu Co Ltd", Power_W=0.1, Supplier Part Number 1=RG16P150KBCT-ND, TempCo="25 ppm/C", Value1=0.1%, Value2=0.1W, Value_Code=150k
R50 R105: "RES, 10.2 k, 1%, 0.1 W, 0603", Manufacturer=Vishay-Dale, Power_W=0.1, Supplier Part Number 1=541-10.2KHCT-ND, TempCo="100 ppm/C", Tolerance_%=1, Value1=1%, Value2=0.1W, Value_Code=10k2, ValueDisplayed=10.2k
R52: "RES, 5.62 k, 0.1%, 0.1 W, 0603", Manufacturer="Susumu Co Ltd", Power_W=0.1, Supplier Part Number 1=RG16P5.62KBCT-ND, TempCo="25 ppm/C", Value1=0.1%, Value2=0.1W, Value_Code=5k62, ValueDisplayed=5.62k
R53: "RES, 7.32 k, 0.1%, 0.1 W, 0603", Manufacturer="Yageo America", Power_W=0.1, TempCo="25 ppm/C", Value1=0.1%, Value2=0.1W, Value_Code=7k32, ValueDisplayed=7.32k
R54: "RES, 499 k, 0.5%, 0.1 W, 0603", Manufacturer="Yageo America", Power_W=0.1, TempCo="50 ppm/C", Tolerance_%=0.5, Value1=0.5%, Value2=0.1W, Value_Code=499k
R61: "RES, 3.32, 1%, 0.1 W, 0603", Manufacturer="Yageo America", Power_W=0.1, Supplier Part Number 1=311-3.32HRCT-ND, TempCo="200 ppm/C", Tolerance_%=1, Value1=1%, Value2=0.1W, Value_Code=3R32, ValueDisplayed=3.32
R65 R112 R124: "RES, 100 k, 1%, 0.1 W, 0603", Manufacturer="Yageo America", Power_W=0.1, Supplier Part Number 1=311-100KHRCT-ND, TempCo="200 ppm/C", Tolerance_%=1, Value1=1%, Value2=0.1W, Value_Code=100k
R67: "RES, 0.1, 1%, 0.5 W, 1206", Manufacturer=Panasonic, Power_W=0.5, Supplier Part Number 1=1577547, TempCo="150 ppm/C", Tolerance_%=1, Value1=1%, Value2=0.5W, Value_Code=R100, ValueDisplayed=0.1
R70 R129: "RES, 33.0, 1%, 0.1 W, 0603", Manufacturer="Yageo America", Power_W=0.1, Supplier Part Number 1=311-33.0HRCT-ND, TempCo="200 ppm/C", Tolerance_%=1, Value1=1%, Value2=0.1W, Value_Code=33R0, ValueDisplayed=33.0
R74 R75: "RES, 240 k, 1%, 0.063 W, 0402", Manufacturer=Vishay-Dale, Power_W=0.063, Supplier Part Number 1=541-240KLCT-ND, TempCo="100 ppm/C", Tolerance_%=1, Value1=1%, Value2=0.063W, Value_Code=240k
R76 R77 R79: "RES, 10.0 k, 1%, 0.063 W, 0402", Manufacturer=Vishay-Dale, Power_W=0.063, Supplier Part Number 1=541-10.0KLCT-ND, TempCo="100 ppm/C", Tolerance_%=1, Value1=1%, Value2=0.063W, Value_Code=10k0, ValueDisplayed=10.0k
R78: "RES, 178 k, 1%, 0.1 W, 0603", Manufacturer="Yageo America", Power_W=0.1, Supplier Part Number 1=311-178KHRCT-ND, TempCo="200 ppm/C", Tolerance_%=1, Value1=1%, Value2=0.1W, Value_Code=178k
R80 R81 R82 R109 R110 R113: "RES, 10.0, 1%, 0.1 W, 0603", Manufacturer=Vishay-Dale, Power_W=0.1, Supplier Part Number 1=541-10.0HCT-ND, TempCo="100 ppm/C", Tolerance_%=1, Value1=1%, Value2=0.1W, Value_Code=10R0, ValueDisplayed=10.0
R83: "RES, 47 k, 5%, 0.063 W, 0402", Manufacturer=Vishay-Dale, Power_W=0.063, Supplier Part Number 1=541-47KJCT-ND, TempCo="200 ppm/C", Tolerance_%=5, Value1=5%, Value2=0.063W, Value_Code=47k0, ValueDisplayed=47k
R85 R86: "RES, 49.9, 1%, 0.1 W, 0603", Manufacturer=Vishay-Dale, Power_W=0.1, Supplier Part Number 1=541-49.9HCT-ND, TempCo="100 ppm/C", Tolerance_%=1, Value1=1%, Value2=0.1W, Value_Code=49R9, ValueDisplayed=49.9
R88: "RES, 10.0, 1%, 0.063 W, 0402", Manufacturer=Vishay-Dale, Power_W=0.063, Supplier Part Number 1=541-10.0LCT-ND, TempCo="100 ppm/C", Tolerance_%=1, Value1=1%, Value2=0.063W, Value_Code=10R0, ValueDisplayed=10.0
R91: "RES, 7.50, 1%, 0.25 W, 1206", Manufacturer="Yageo America", Power_W=0.25, Supplier Part Number 1=311-7.50FRCT-ND, TempCo="200 ppm/C", Tolerance_%=1, Value1=1%, Value2=0.25W, Value_Code=7R50, ValueDisplayed=7.50
R92: "RES, 3.90, 1%, 0.25 W, 1206", Manufacturer="Yageo America", Power_W=0.25, Supplier Part Number 1=311-3.90FRCT-ND, TempCo="200 ppm/C", Tolerance_%=1, Value1=1%, Value2=0.25W, Value_Code=3R90, ValueDisplayed=3.90
R93: "RES, 2.00, 1%, 0.25 W, 1206", Manufacturer="Yageo America", Power_W=0.25, Supplier Part Number 1=311-2.00FRCT-ND, TempCo="200 ppm/C", Tolerance_%=1, Value1=1%, Value2=0.25W, Value_Code=2R00, ValueDisplayed=2.00
R94: "RES, 118 k, 0.5%, 0.0625 W, 0603", Manufacturer="Susumu Co Ltd", Power_W=0.0625, Supplier Part Number 1=RR08P118KDCT-ND, TempCo="25 ppm/C", Tolerance_%=0.5, Value1=0.5%, Value2=0.0625W, Value_Code=118k
R95: "RES, 22.1 k, 0.5%, 0.0625 W, 0603", Manufacturer="Susumu Co Ltd", Power_W=0.0625, Supplier Part Number 1=RR08P22.1KDCT-ND, TempCo="25 ppm/C", Tolerance_%=0.5, Value1=0.5%, Value2=0.0625W, Value_Code=22k1, ValueDisplayed=22.1k
R96 R97: "RES, 49.9 k, 1%, 0.1 W, 0603", Manufacturer="Yageo America", Power_W=0.1, Supplier Part Number 1=311-49.9KHRCT-ND, TempCo="200 ppm/C", Tolerance_%=1, Value1=1%, Value2=0.1W, Value_Code=49k9, ValueDisplayed=49.9k
R98: "RES, 28.7 k, 1%, 0.1 W, 0603", Manufacturer="Yageo America", Power_W=0.1, Supplier Part Number 1=311-28.7KHRCT-ND, TempCo="200 ppm/C", Tolerance_%=1, Value1=1%, Value2=0.1W, Value_Code=28k7, ValueDisplayed=28.7k
R100: "RES, 150 k, 1%, 0.1 W, 0603", Manufacturer="Yageo America", Power_W=0.1, Supplier Part Number 1=311-150KHRCT-ND, TempCo="200 ppm/C", Tolerance_%=1, Value1=1%, Value2=0.1W, Value_Code=150k
R101: "RES, 23.7 k, 1%, 0.1 W, 0603", Manufacturer=Vishay-Dale, Power_W=0.1, Supplier Part Number 1=541-23.7KHCT-ND, TempCo="100 ppm/C", Tolerance_%=1, Value1=1%, Value2=0.1W, Value_Code=23k7, ValueDisplayed=23.7k
R102: "RES, 19.1 k, 1%, 0.1 W, 0603", Manufacturer=Vishay-Dale, Power_W=0.1, Supplier Part Number 1=541-19.1KHCT-ND, TempCo="100 ppm/C", Tolerance_%=1, Value1=1%, Value2=0.1W, Value_Code=19k1, ValueDisplayed=19.1k
R103: "RES, 15.4 k, 1%, 0.1 W, 0603", Manufacturer=Vishay-Dale, Power_W=0.1, Supplier Part Number 1=541-15.4KHCT-ND, TempCo="100 ppm/C", Tolerance_%=1, Value1=1%, Value2=0.1W, Value_Code=15k4, ValueDisplayed=15.4k
R104: "RES, 11.8 k, 1%, 0.1 W, 0603", Manufacturer=Vishay-Dale, Power_W=0.1, Supplier Part Number 1=541-11.8KHCT-ND, TempCo="100 ppm/C", Tolerance_%=1, Value1=1%, Value2=0.1W, Value_Code=11k8, ValueDisplayed=11.8k
R106: library part CRCW06036k65FKEA, "RES, 6.65 k, 1%, 0.1 W, 0603", Manufacturer=Vishay-Dale, Power_W=0.1, Supplier Part Number 1=541-6.65KHCT-ND, TempCo="100 ppm/C", Tolerance_%=1, Value1=1%, Value2=0.1W, Value_Code=6k65, ValueDisplayed=6.65k
R107: "RES, 2.55 k, 1%, 0.1 W, 0603", Manufacturer=Vishay-Dale, Power_W=0.1, Supplier Part Number 1=541-2.55KHCT-ND, TempCo="100 ppm/C", Tolerance_%=1, Value1=1%, Value2=0.1W, Value_Code=2k55, ValueDisplayed=2.55k
R108: "RES, 52.3 k, 1%, 0.1 W, 0603", Manufacturer=Vishay-Dale, Power_W=0.1, Supplier Part Number 1=541-52.3KHCT-ND, TempCo="100 ppm/C", Tolerance_%=1, Value1=1%, Value2=0.1W, Value_Code=52k3, ValueDisplayed=52.3k
R115: "RES, 442 k, 1%, 0.1 W, 0603", Manufacturer="Yageo America", Power_W=0.1, Supplier Part Number 1=311-442KHRCT-ND, TempCo="200 ppm/C", Tolerance_%=1, Value1=1%, Value2=0.1W, Value_Code=442k
R116: "RES, 200 k, 0.1%, 0.1 W, 0603", Manufacturer="Yageo America", Power_W=0.1, TempCo="25 ppm/C", Value1=0.1%, Value2=0.1W, Value_Code=200k
R117: "RES, 44.2 k, 0.5%, 0.0625 W, 0603", Manufacturer="Susumu Co Ltd", Power_W=0.0625, Supplier Part Number 1=RR08P44.2KDCT-ND, TempCo="25 ppm/C", Tolerance_%=0.5, Value1=0.5%, Value2=0.0625W, Value_Code=44k2, ValueDisplayed=44.2k
R120: "RES, 8.66 k, 0.5%, 0.0625 W, 0603", Manufacturer="Susumu Co Ltd", Power_W=0.0625, Supplier Part Number 1=RR08P8.66KDCT-ND, TempCo="25 ppm/C", Tolerance_%=0.5, Value1=0.5%, Value2=0.0625W, Value_Code=8k66, ValueDisplayed=8.66k
R121: "RES, 32.4 k, 0.5%, 0.1 W, 0603", Manufacturer="Yageo America", Power_W=0.1, TempCo="50 ppm/C", Tolerance_%=0.5, Value1=0.5%, Value2=0.1W, Value_Code=32k4, ValueDisplayed=32.4k
R122: "RES, 47.0 k, 1%, 0.1 W, 0603", Manufacturer="Yageo America", Power_W=0.1, Supplier Part Number 1=311-47.0KHRCT-ND, TempCo="200 ppm/C", Tolerance_%=1, Value1=1%, Value2=0.1W, Value_Code=47k0, ValueDisplayed=47.0k
R123: "RES, 24.9 k, 1%, 0.1 W, 0603", Manufacturer=Vishay-Dale, Power_W=0.1, Supplier Part Number 1=541-24.9KHCT-ND, TempCo="100 ppm/C", Tolerance_%=1, Value1=1%, Value2=0.1W, Value_Code=24k9, ValueDisplayed=24.9k
R128: "RES, 1.00 k, 1%, 0.1 W, 0603", Manufacturer=Vishay-Dale, Power_W=0.1, Supplier Part Number 1=541-1.00KHCT-ND, TempCo="100 ppm/C", Tolerance_%=1, Value1=1%, Value2=0.1W, Value_Code=1k00, ValueDisplayed=1.00k
R130: "RES, 35.7, 1%, 0.25 W, 1206", Manufacturer="Yageo America", Power_W=0.25, Supplier Part Number 1=311-35.7FRCT-ND, TempCo="100 ppm/C", Tolerance_%=1, Value1=1%, Value2=0.25W, Value_Code=35R7, ValueDisplayed=35.7
R131 R132 R133 R134 R135 R136: library part CMP-0077662-1, "RES, 2.20, 1%, 1 W, AEC-Q200 Grade 0, 2.2x5.8mm", Manufacturer=Vishay/Beyschlag, Power_W=1W, Supplier Part Number 1=MMB-2.2BCT-ND, TempCo="50 ppm/C", Tolerance_%=1%, Value_Code=2R20, ValueDisplayed=2.20
R137: "RES, 61.9 k, 1%, 0.1 W, 0603", Manufacturer="Yageo America", Power_W=0.1, Supplier Part Number 1=311-61.9KHRCT-ND, TempCo="200 ppm/C", Tolerance_%=1, Value1=1%, Value2=0.1W, Value_Code=61k9, ValueDisplayed=61.9k
R138: "RES, 1.0, 5%, 0.1 W, 0603", Manufacturer=Vishay-Dale, Power_W=0.1, Supplier Part Number 1=541-1.0GCT-ND, TempCo="200 ppm/C", Tolerance_%=5, Value1=5%, Value2=0.1W, Value_Code=1R00, ValueDisplayed=1.0
SH-J3 SH-J5 SH-J8 SH-J11 SH-J12 SH-J17 SH-J18 SH-J20 SH-J21 SH-J22: "Shunt, 100mil, Gold plated, Black", Alternate Manufacturer=Samtec, Alternate PartNumber=SNT-100-BK-G, Manufacturer=3M, Supplier Part Number 1=3M9580-ND
TP1 TP2 TP3 TP4 TP5 TP6 TP7 TP8 TP9 TP10 TP11 TP12 TP13 TP14 TP15 TP16 TP17 TP18 TP19 TP20 TP21 TP22 TP23 TP24 TP25 TP26 TP27 TP28 TP29 TP30: "PIGTAIL", Manufacturer="Texas Instruments"
TP31: library part TP_SM_1MM, "1mm Test Point, SMT", Manufacturer=Any
U1 U2 U15 U16: "High-Accuracy, Low-Power, Digital Temperature Sensor with SMBus and Two-Wire Serial Interface, DRV0006A (WSON-6)", Alternate Manufacturer="Texas Instruments", Alternate PartNumber=TMP116AIDRVT
U3: "2A LED Driver with Integrated NFET, High-Side Current Sense, and Shunt PWM Dimming Capable, DGQ0010E (VSSOP-10)", Alternate Manufacturer="Texas Instruments", Alternate PartNumber=TPS92515HVDGQT
U4: "12-bit, single-channel, ultra-low power DAC in 6-pin SC70 package for battery powered applications, DCK0006A (SOT-SC70-6)", Alternate Manufacturer="Texas Instruments", Alternate PartNumber=DAC7311IDCKT
U6: "Single 2-Input Positive-NOR Gate, DRL0005A, LARGE T&R", Alternate Manufacturer="Texas Instruments", Alternate PartNumber=Equivalent, F @ Nom Voltage(Max)(Mhz)=150, Generic Part Number=SN74LVC1G02, ICC @ Nom Voltage(Max)(mA)=0.01, Operating Temperature Range(C)="-40 to 125,-40 to 85", Rating=Catalog, Supplier Part Number 1=595-SN74LVC1G02DRLR, tpd @ Nom Voltage(Max)(ns)=8,5.5,4.5,4, Voltage(Nom)(V)=1.8,2.5,3.3,5
U7 U12: "Single D-Type Flip-Flop with Asynchronous Clear, DRY0006A, LARGE T&R", Alternate Manufacturer="Texas Instruments", Alternate PartNumber=Equivalent, F @ Nom Voltage(Max)(Mhz)=150, Generic Part Number=SN74LVC1G175, ICC @ Nom Voltage(Max)(mA)=0.01, Operating Temperature Range(C)="-40 to 125,-40 to 85", Rating=Catalog, Supplier Part Number 1=595-SN74LVC1G175DRYR, tpd @ Nom Voltage(Max)(ns)=13.4,7.1,5.7,4, Voltage(Nom)(V)=1.8,2.5,3.3,5
U8: "60-V, High-Side, High-Speed, Current Output Current Shunt Monitor, DBV0005A (SOT-23-5)", Alternate Manufacturer="Texas Instruments", Alternate PartNumber=INA169NA/250
U9: "Single Output LDO, 50 mA, Adjustable 1.175 to 48 V Output, 7 to 50 V Input, 8-pin MSOP (DGN), -40 to 125 degC, Green (RoHS & no Sb/Br)", Alternate Manufacturer="Texas Instruments", Alternate PartNumber=Equivalent, Supplier Part Number 1=296-30081-2-ND
U10: "Phase Dimmable, Single Stage Boost Controller for LED Lighting, DGN0008D (VSSOP-8)", Alternate Manufacturer="Texas Instruments", Alternate PartNumber=TPS92561DGN
U11 U18 U20: "4A/8A Single Channel High-speed Low-side Gate Driver, DBV0006A (SOT-23-6)", Alternate Manufacturer="Texas Instruments", Alternate PartNumber=UCC27511DBVT
U13 U14 U33: "40ns, micro-Power, Rail-to-Rail Input, Single-Channel Comparator with Push-Pull Outputs, DCK0005A (SOT-SC70-5)", Alternate Manufacturer="Texas Instruments", Alternate PartNumber=TLV3201AIDCKT
U17: "Single Schmitt-Trigger Inverter, DRL0005A, LARGE T&R", Alternate Manufacturer="Texas Instruments", Alternate PartNumber=Equivalent, F @ Nom Voltage(Max)(Mhz)=150, Generic Part Number=SN74LVC1G14, ICC @ Nom Voltage(Max)(mA)=0.01, Operating Temperature Range(C)="-40 to 125,-40 to 85", Rating=Catalog, Supplier Part Number 1=595-SN74LVC1G14DRLR, tpd @ Nom Voltage(Max)(ns)=11,6.5,5.5,5, Voltage(Nom)(V)=1.8,2.5,3.3,5
U19: "Single Schmitt-Trigger Buffer, DCK0005A, LARGE T&R", Alternate Manufacturer="Texas Instruments", Alternate PartNumber=Equivalent, F @ Nom Voltage(Max)(Mhz)=150, Generic Part Number=SN74LVC1G17, ICC @ Nom Voltage(Max)(mA)=0.01, Operating Temperature Range(C)="-40 to 125,-40 to 85", Rating=Catalog, Supplier Part Number 1=595-SN74LVC1G17DCKR, tpd @ Nom Voltage(Max)(ns)=11,6.5,5.5,5, Voltage(Nom)(V)=1.8,2.5,3.3,5
U21: "25 MHz Mixed Signal Microcontroller with 32 KB Flash, 2048 B SRAM and 29 GPIOs, -40 to 85 degC, 40-pin QFN (RSB), Green (RoHS & no Sb/Br)", Alternate Manufacturer="Texas Instruments", Alternate PartNumber=Equivalent, Frequency(MHz)=25, Pin/Package="38TSSOP, 40WQFN", Temp Sensor=Yes
U22: "High-Performance, 5000-VRMS Reinforced Quad-Channel Digital Isolators With Integrated High-Efficiency, Low-Emissions DC-DC Converter, DWE0016A (SOIC-16)", Alternate Manufacturer="Texas Instruments", Alternate PartNumber=ISOW7842DWE
U23 U24 U25 U26: "ESD in 0402 Package with 10 pF Capacitance and 6 V Breakdown, 1 Channel, -40 to +125 degC, 2-pin X2SON (DPY), Green (RoHS & no Sb/Br)", Alternate Manufacturer="Texas Instruments", Alternate PartNumber=Equivalent, Breakdown Voltage(Min)(V)=6, IO Capacitance(Typ)(pF)=10, Supplier Part Number 1=296-30406-2-ND
U27: "60V 2A Industrial eFuse With Integrated Reverse-Input Polarity Protection, PWP0016H (TSSOP-16)", Alternate Manufacturer="Texas Instruments", Alternate PartNumber=TPS26602PWPT
U28: "8-Bit Micro Power DUAL Digital-to-Analog Converter with Rail-to-Rail Output, 10-pin LLP, Pb-Free", Manufacturer="Texas Instruments", PackageTopMarking=ZXYTT*X77C, PowerWise=Y, Supplier Part Number 1=DAC082S085CISDTR-ND
U29: "250-mA Ultra-Low-Noise, Low-IQ LDO, DBV0005A (SOT-23-5)", Alternate Manufacturer="Texas Instruments"
U30: "2.5 V, 50 ppm / degC, 50 uA Series (Bandgap) Voltage Reference, -40 to 125 degC, 3-pin SOT-23 (DBZ), Green (RoHS & no Sb/Br)", Alternate Manufacturer="Texas Instruments", Alternate PartNumber=Equivalent, Rating=Catalog, Supplier Part Number 1=296-26322-2-ND, Temp Coeff(Max)(ppm/ degree C)=50, Temp Coeff(Typ)(ppm/ degree C)=20
U31: "3V-65V, 150mA Synchronous Buck Converter With Ultra-Low IQ, DRC0010J (VSON-10)", Alternate Manufacturer="Texas Instruments", Alternate PartNumber=LM5165DRCT
U32: "12-V, 2-A, 65-mohm¸ On-Resistance Load Switch, DRV0006A (WSON-6)", Alternate Manufacturer="Texas Instruments"
ZZ1: library part AssemblyNoteLabel, Alternate Manufacturer=-
ZZ2 ZZ3 ZZ4 ZZ5 ZZ6 ZZ7 ZZ8 ZZ9 ZZ10 ZZ11 ZZ12 ZZ13 ZZ14: library part AssemblyNote, Alternate Manufacturer=-

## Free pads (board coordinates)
  round 60 hole 30: 1(6919.3,2104.09) 2(6819.3,2104.09)
  round 60 hole 39.37: 1(7210.24,2004.09) 2(7210.24,2104.09)
  round 60 hole 157.48 unplated: 1(7568.31,1534.09)
  round 314.96 hole 125.98: 2(196.85,196.85) 2(196.85,2952.76) 2(2362.04,196.85) 2(2362.2,2952.76) 2(2755.91,196.85) 2(2755.91,2952.76) 2(4921.26,196.85) 2(4921.26,2952.76)
  round 0 hole 125.98 unplated: 3(1279,1575)

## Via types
v1: diameter 32, hole 20, Top Layer to Bottom Layer, tented both sides, 779 vias
v2: diameter 26, hole 12, Top Layer to Bottom Layer, tented both sides, 622 vias
v3: diameter 24, hole 12, Top Layer to Bottom Layer, 506 vias
v4: diameter 19.68, hole 7.87, Top Layer to Bottom Layer, 50 vias
v5: diameter 26, hole 12, Top Layer to Bottom Layer, 14 vias
v6: diameter 19.68, hole 7.87, Top Layer to Bottom Layer, tented both sides, 12 vias
v7: diameter 19.68, hole 7.87, Top Layer to Bottom Layer, tented top, 4 vias

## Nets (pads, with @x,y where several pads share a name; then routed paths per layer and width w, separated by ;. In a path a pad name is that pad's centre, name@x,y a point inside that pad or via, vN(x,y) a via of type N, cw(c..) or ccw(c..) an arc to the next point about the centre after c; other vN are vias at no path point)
5V-BUCK_OUT: C83.1 C86.1 C87.1 C89.1 L5.2 R112.2 R113.2 R118.2 TP22.1 U32.6 | length 2795.3
  Top Layer w12: 4995,1620 4996.61,1621.61 U32.6@4996.61,1654.41
  Top Layer w20: v2(4900,1770) 4906,1770 4927.5,1748.5 R113.2@4940,1748.5 ; C89.1@4993.07,1560 4995,1561.93 4995,1620
  Top Layer w25: R112.2@5100,902.33 5098,900.33 5098,780 ; R118.2@5135,780.47 5098.47,780.47 5098,780 ; 5148,695 5098,745 5098,780 ; C86.1@5410,853.07 5410,805 5417.5,797.5 v2@5417.5,792.97
  Top Layer w50: 4938.7,1403.7 4993.07,1458.07 C89.1@4993.07,1560 ; v2(5120,695) 5148,695 5183,660 5355,660 5417.5,722.5 v2@5417.5,792.97
  VCC w20: v2(4900,1770) 4960,1710
  VCC w25: v2(5420,785) 5420,1255 TP22.1@5450,1285
  VCC w40: 4960,1425 4960,1710
  VCC w50: 4960,1425 v2(4960,1280) 5170,1070 5170,968 5110,908 5110,695 v2(5120,695)
  other v2: 4980,1255 4960,1310
5V-LS_ON: R124.2 U21.36 U32.5 | length 4914.8
  Top Layer w6: v2(3065,2000) 3063,1998 2927,1998 2785,2140 2785,2340 2981,2536 2981,2764.94 3035.06,2819 3398.03,2819 3408.03,2829 3447.97,2829 3469.97,2807 3531.09,2807 3628,2903.91 3628,2944.11 3640.89,2957 3659.11,2957 3687.11,2929 4564,2929 v2(4580,2945) ; U21.36@3192.87,2193.54 3192.87,2107.13 3225,2075 v2(3225,2060) 3230,2060 v2@3235,2065
  Top Layer w10: v2(4890,1675) 4923.5,1675 R124.2@4940,1691.5 4951.5,1680 U32.5@4996.61,1680
  Bottom Layer w6: v2(3065,2000) 3065,2026.76 3083.24,2045 3170,2045 3185,2060 v2(3225,2060) ; v2(4580,2945) 4585,2950 v2@4590,2950 ; v2@4590,2945 4590,2930 4652.08,2867.92 4652.08,2850.95 4679.03,2824 4693.17,2824 4851.17,2666 5030.06,2666 5038,2658.06 5038,2350 5013,2325 5013,2284.12 5026,2271.12 5026,2228.88 5003.15,2206.03 5003.15,2163.3 4975,2135.14 4975,1760 v2(4890,1675)
+2V5REF: C80.1 R42.2 R43.2 R88.2 R109.1 R126.1 TP21.1 U30.2 | length 4486.1
  Top Layer w10: v2(3510,785) 3511,786 3722,786 3725,789
  Top Layer w12: R88.2@3095,1931.38 3095,1900 v2(3100,1895) ; v2(3465,1920) 3550,2005 R109.1@3567.22,2005 ; 3950,755 3960,765 4077.06,765 4077.24,765.18 4138.5,765.18 R43.2@4138.5,765 ; v2(4350,2615) R126.1@4388.5,2615
  Top Layer w20: TP21.1@2980,1830 3035,1830 v2(3100,1895) ; v2(3100,1775) v2(3100,1895) ; U30.2@3137.6,1857.24 C80.1@3137.6,1904.09 ; C80.1@3148.5,1915 C80.1@3137.6,1904.09 ; v2(3510,785) 3513.82,781.18 R42.2@3513.82,730 ; 3725,789 3779,735 3930,735 3950,755 ; R43.2@4138.5,762.82 R43.2@4138.5,765 ; v2(3100,1895) 3128.5,1895 C80.1@3137.6,1904.09
  VCC w20: v2(3100,1895) 3190,1895 3345,2050 3345,2155 3455,2265 3455,2275 3645,2465 3645,2510 3750,2615 v2(4350,2615)
  Bottom Layer w12: v2(3100,1895) 3125,1920 v2(3465,1920)
  Bottom Layer w20: v2(3100,1775) 3100,1461.34 3471,1090.34 3471,956.99 3477,950.99 3477,818 v2(3510,785)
